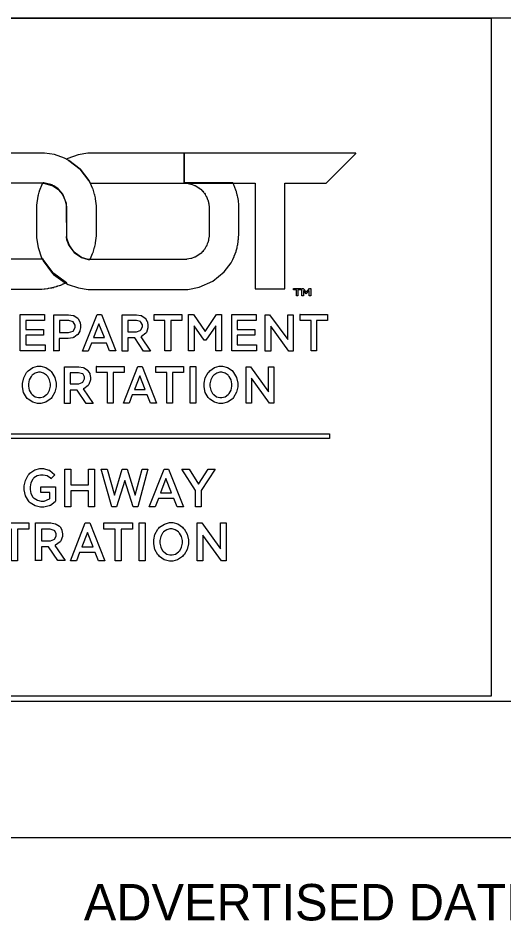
# Model space of a CAD drawing. Extents: x 0 to 34, y 0 to 22.
# Drawn here: x 28.747 to 30.08, y 2.522 to 5 of the extents above; entities that cross this region are included whole.
import ezdxf

# ---------------------------------------------------------------- set-up
doc = ezdxf.new("R2010")
doc.units = 0
for name, color, linetype in [('BORD-LINE', 7, 'Continuous'), ('MSHA-LOGO', 7, 'Continuous'), ('TTLB-TEXT', 7, 'Continuous'), ('USER-LINE', 7, 'Continuous')]:
    doc.layers.add(name, color=color, linetype=linetype)

msp = doc.modelspace()

# ---------------------------------------------------------------- linework, layer by layer
at = {"layer": 'BORD-LINE'}
for p, q in [((33.5, 5), (27.437, 5)), ((33.5, 2.75), (27.437, 2.75))]:
    msp.add_line(p, q, dxfattribs=at)
msp.add_lwpolyline([(27.437, 2.75), (27.437, 3.125), (33.5, 3.125)], dxfattribs=at)
at = {"layer": 'MSHA-LOGO'}
for points in [[(28.502, 4.5475), (28.8109, 4.5475), (28.8111, 4.5474), (28.8136, 4.547), (28.8145, 4.547), (28.817, 4.5469), (28.8399, 4.5408), (28.842, 4.5398), (28.8446, 4.5385), (28.856, 4.5303), (28.8657, 4.5202), (28.8674, 4.518), (28.8692, 4.5154), (28.8759, 4.5014), (28.8796, 4.486), (28.8798, 4.4828), (28.8798, 4.4828), (28.8798, 4.4822), (28.8798, 4.4822), (28.8798, 4.4815), (28.8798, 4.4797), (28.8798, 4.4791), (28.8798, 4.4081), (28.8798, 4.4074), (28.8798, 4.4056), (28.8798, 4.405), (28.8798, 4.405), (28.8798, 4.4045), (28.8798, 4.4045), (28.8798, 4.403), (28.8793, 4.3995), (28.8793, 4.3983), (28.8801, 4.3924), (28.8867, 4.3754), (28.901, 4.3568), (28.9214, 4.3432), (28.9399, 4.3375), (28.9439, 4.3373), (28.9446, 4.3384), (28.9451, 4.3392), (28.9451, 4.3392), (28.9458, 4.3405), (28.9518, 4.3539), (28.9524, 4.3553), (28.9529, 4.3567), (28.9572, 4.3708), (28.9576, 4.3724), (28.9577, 4.3732), (28.9595, 4.3804), (28.9596, 4.3812), (28.96, 4.3834), (28.9622, 4.4023), (28.9622, 4.4086), (28.9622, 4.4781), (28.9622, 4.485), (28.96, 4.5034), (28.9596, 4.5055), (28.9595, 4.5063), (28.9578, 4.5136), (28.9576, 4.5144), (28.9572, 4.5158), (28.9529, 4.5301), (28.9524, 4.5315), (28.9518, 4.5329), (28.9458, 4.5463), (28.9451, 4.5475), (28.9415, 4.5545), (28.9175, 4.5853), (28.8868, 4.6092), (28.8798, 4.6128), (28.8747, 4.6156), (28.8469, 4.6252), (28.8199, 4.6294), (28.8109, 4.6294), (28.5637, 4.6294)], [(28.8798, 4.4392), (28.8798, 4.4781), (28.8798, 4.4792), (28.8798, 4.4815), (28.8798, 4.4822), (28.8798, 4.4838), (28.8803, 4.4873), (28.8803, 4.4885), (28.8799, 4.4912), (28.87, 4.5163), (28.8684, 4.5185), (28.8667, 4.5209), (28.8568, 4.5312), (28.8451, 4.5395), (28.8425, 4.5408), (28.8403, 4.542), (28.8175, 4.548), (28.8151, 4.5481), (28.8151, 4.5478), (28.8145, 4.547), (28.8135, 4.5451), (28.8053, 4.5247), (28.8047, 4.5227), (28.8044, 4.522), (28.8023, 4.5146), (28.8021, 4.5139), (28.8015, 4.511), (28.7979, 4.4863), (28.7979, 4.4781), (28.7979, 4.4392), (28.7979, 4.4351)], [(29.353, 4.4781), (29.353, 4.4803), (29.3526, 4.4861), (29.3525, 4.4869), (29.3525, 4.4874), (29.3525, 4.4895), (29.3525, 4.4911), (29.3519, 4.4946), (29.3519, 4.4957), (29.3519, 4.4961), (29.3519, 4.497), (29.3519, 4.4973), (29.3519, 4.4975), (29.3519, 4.4981), (29.3519, 4.4983), (29.3518, 4.4988), (29.351, 4.504), (29.3509, 4.5045), (29.3509, 4.5051), (29.3504, 4.5062), (29.3504, 4.5066), (29.3502, 4.5072), (29.3489, 4.5128), (29.3488, 4.5133), (29.3488, 4.5139), (29.3488, 4.5144), (29.3486, 4.5152), (29.3465, 4.5229), (29.3463, 4.5237), (29.3459, 4.525), (29.341, 4.5379), (29.3405, 4.5392), (29.3403, 4.5399), (29.3372, 4.5464), (29.3369, 4.547), (29.3369, 4.5473), (29.3364, 4.5481), (29.2053, 4.5481), (29.2048, 4.547), (29.2063, 4.547), (29.2068, 4.547), (29.2075, 4.547), (29.2092, 4.5466), (29.2094, 4.5465), (29.2105, 4.5464), (29.221, 4.5443), (29.2219, 4.5439), (29.2228, 4.5437), (29.2313, 4.5407), (29.2322, 4.5403), (29.2328, 4.54), (29.2374, 4.5375), (29.2379, 4.5372), (29.2383, 4.5372), (29.2384, 4.5372), (29.2388, 4.5369), (29.2432, 4.5343), (29.2436, 4.534), (29.2441, 4.5337), (29.2441, 4.5335), (29.2445, 4.5333), (29.2484, 4.5303), (29.2488, 4.5299), (29.2493, 4.5294), (29.2497, 4.5292), (29.2527, 4.526), (29.253, 4.5258), (29.2533, 4.5253), (29.2535, 4.5253), (29.254, 4.5247), (29.2542, 4.5245), (29.2564, 4.5219), (29.2566, 4.5216), (29.2571, 4.5211), (29.2572, 4.521), (29.258, 4.5197), (29.2582, 4.5196), (29.2584, 4.5193), (29.2606, 4.5162), (29.2607, 4.5159), (29.2609, 4.5158), (29.2616, 4.5141), (29.2618, 4.5139), (29.2621, 4.5133), (29.2623, 4.5133), (29.2624, 4.5131), (29.2637, 4.5105), (29.2639, 4.5102), (29.2639, 4.51), (29.2647, 4.5079), (29.2649, 4.5076), (29.265, 4.5074), (29.2663, 4.5044), (29.2664, 4.504), (29.2665, 4.5039), (29.2669, 4.5019), (29.2669, 4.5017), (29.2673, 4.501), (29.2675, 4.5009), (29.2676, 4.5007), (29.2685, 4.4985), (29.2685, 4.4978), (29.2686, 4.4975), (29.2694, 4.4944), (29.2695, 4.4942), (29.2695, 4.4934), (29.2701, 4.4916), (29.2701, 4.4911), (29.2702, 4.4907), (29.2706, 4.4878), (29.2706, 4.4869), (29.2706, 4.4862), (29.2711, 4.4848), (29.2711, 4.4843), (29.2711, 4.4826), (29.2716, 4.4789), (29.2716, 4.4776), (29.2716, 4.4066), (29.2716, 4.4049), (29.2712, 4.4004), (29.2711, 4.3998), (29.2711, 4.3992), (29.2707, 4.3975), (29.2706, 4.3973), (29.2706, 4.3962), (29.2701, 4.3939), (29.2701, 4.3931), (29.2701, 4.3923), (29.2695, 4.3906), (29.2695, 4.39), (29.2694, 4.3897), (29.2686, 4.3866), (29.2685, 4.3864), (29.2684, 4.3861), (29.2676, 4.3835), (29.2675, 4.3832), (29.2675, 4.383), (29.2671, 4.3824), (29.2669, 4.3822), (29.2664, 4.3807), (29.2664, 4.3801), (29.2663, 4.3799), (29.265, 4.3769), (29.2649, 4.3765), (29.2647, 4.3763), (29.2639, 4.3742), (29.2639, 4.3739), (29.2637, 4.3737), (29.2624, 4.3711), (29.2623, 4.3708), (29.2619, 4.3703), (29.2618, 4.3703), (29.2616, 4.3702), (29.2609, 4.3685), (29.2607, 4.3682), (29.2605, 4.368), (29.2584, 4.3649), (29.2582, 4.3646), (29.258, 4.3645), (29.2572, 4.3632), (29.2571, 4.363), (29.2566, 4.3625), (29.2563, 4.3623), (29.2541, 4.3597), (29.254, 4.3594), (29.2535, 4.3589), (29.2531, 4.3584), (29.253, 4.3584), (29.2527, 4.3581), (29.2496, 4.355), (29.2493, 4.3547), (29.2488, 4.3542), (29.2484, 4.354), (29.2445, 4.3509), (29.2441, 4.3506), (29.2436, 4.3502), (29.2436, 4.3501), (29.2432, 4.3498), (29.239, 4.3472), (29.2384, 4.347), (29.238, 4.347), (29.2379, 4.347), (29.2375, 4.3467), (29.2328, 4.3441), (29.2322, 4.3439), (29.2315, 4.3435), (29.2228, 4.3405), (29.2219, 4.3402), (29.2208, 4.34), (29.2105, 4.3378), (29.2094, 4.3377), (29.2088, 4.3377), (29.2071, 4.3373), (29.2068, 4.3371), (29.2059, 4.3371), (29.2039, 4.3371), (29.2032, 4.3371), (28.9498, 4.3371), (28.9489, 4.3371), (28.9468, 4.3371), (28.9462, 4.3371), (28.9399, 4.3375), (28.9214, 4.3432), (28.9011, 4.3573), (28.887, 4.3774), (28.8812, 4.3957), (28.8809, 4.4019), (28.8809, 4.403), (28.8809, 4.4053), (28.8809, 4.4061), (28.8809, 4.4392), (28.8798, 4.4392)], [(28.7979, 4.4351), (28.7979, 4.4061), (28.7979, 4.3971), (28.8023, 4.37), (28.8119, 4.3423), (28.8145, 4.3371), (28.8163, 4.3336), (28.8393, 4.3022), (28.842, 4.2993), (28.8447, 4.2966), (28.8763, 4.2737), (28.8798, 4.2718), (28.885, 4.2691), (28.9127, 4.2595), (28.9397, 4.2553), (28.9487, 4.2553), (29.2022, 4.2553), (29.2127, 4.2553), (29.2443, 4.2612), (29.2817, 4.2779), (29.3129, 4.3038), (29.3317, 4.3282), (29.3364, 4.3371), (29.3368, 4.3378), (29.3397, 4.3442), (29.34, 4.3449), (29.3405, 4.3462), (29.3453, 4.3591), (29.3457, 4.3604), (29.346, 4.3612), (29.3482, 4.369), (29.3483, 4.3698), (29.3483, 4.3703), (29.3483, 4.3708), (29.3484, 4.3713), (29.3497, 4.377), (29.3499, 4.3776), (29.3499, 4.3781), (29.3504, 4.3793), (29.3504, 4.3796), (29.3505, 4.3802), (29.3513, 4.3853), (29.3514, 4.3858), (29.3514, 4.3861), (29.3514, 4.3867), (29.3514, 4.3869), (29.3514, 4.3873), (29.3514, 4.3882), (29.3514, 4.3884), (29.3514, 4.39), (29.3519, 4.3935), (29.3519, 4.3947), (29.3519, 4.3967), (29.3519, 4.3973), (29.3519, 4.3995), (29.3525, 4.4044), (29.3525, 4.4061), (29.353, 4.4781)], [(28.4062, 4.2563), (28.8104, 4.2563), (28.8127, 4.2563), (28.8189, 4.2567), (28.8197, 4.2568), (28.8219, 4.2568), (28.8277, 4.2577), (28.8285, 4.2578), (28.8292, 4.2578), (28.8306, 4.2584), (28.8311, 4.2584), (28.8316, 4.2585), (28.8363, 4.2593), (28.8368, 4.2594), (28.8376, 4.2594), (28.8393, 4.2599), (28.8399, 4.2599), (28.8403, 4.2601), (28.8447, 4.2608), (28.8451, 4.2609), (28.8453, 4.2611), (28.8479, 4.2619), (28.8482, 4.262), (28.8486, 4.2621), (28.8525, 4.2634), (28.8529, 4.2635), (28.8531, 4.2637), (28.8557, 4.2645), (28.856, 4.2646), (28.8564, 4.2647), (28.8602, 4.266), (28.8606, 4.2661), (28.8609, 4.2663), (28.8635, 4.2671), (28.8637, 4.2672), (28.8641, 4.2673), (28.8685, 4.2691), (28.8689, 4.2692), (28.8692, 4.2694), (28.8712, 4.2702), (28.8715, 4.2703), (28.8722, 4.2706), (28.8782, 4.2735), (28.8788, 4.2739), (28.8792, 4.2737), (28.8808, 4.2734), (28.8814, 4.2734), (28.8811, 4.2734), (28.8805, 4.2738), (28.8803, 4.2739), (28.8768, 4.2757), (28.8457, 4.2985), (28.843, 4.3014), (28.8403, 4.3041), (28.8179, 4.3348), (28.8161, 4.3382), (28.8157, 4.3382), (28.8148, 4.3382), (28.8145, 4.3382), (28.8136, 4.3382), (28.8116, 4.3382), (28.8109, 4.3382), (28.5108, 4.3382)]]:
    msp.add_lwpolyline(points, dxfattribs=at)
for points in [[(28.9457, 4.5465), (28.947, 4.5465), (28.9477, 4.5465), (29.2011, 4.5465), (29.2015, 4.5465), (29.2024, 4.5465), (29.2027, 4.5465), (29.2032, 4.5475), (29.2032, 4.6289), (29.2031, 4.6289), (29.2016, 4.6289), (29.2011, 4.6289), (28.9477, 4.6289), (28.9387, 4.6289), (28.9117, 4.6245), (28.884, 4.6149), (28.8799, 4.6128), (28.8868, 4.6092), (28.9175, 4.5853), (28.9415, 4.5545), (28.9451, 4.5475)], [(29.2032, 4.6289), (29.2032, 4.547), (29.3975, 4.547), (29.3975, 4.2568), (29.4789, 4.2568), (29.4789, 4.547), (29.5924, 4.547), (29.6738, 4.6284), (29.6738, 4.6289)], [(29.5027, 4.2577), (29.5229, 4.2577), (29.5229, 4.2541), (29.5151, 4.2541), (29.5151, 4.2375), (29.511, 4.2375), (29.511, 4.2541), (29.5027, 4.2541)], [(29.526, 4.2577), (29.5297, 4.2577), (29.5384, 4.2479), (29.5467, 4.2577), (29.5504, 4.2577), (29.5504, 4.2375), (29.5457, 4.2375), (29.5457, 4.252), (29.5379, 4.2427), (29.5302, 4.252), (29.5302, 4.2375), (29.526, 4.2375)], [(28.7529, 4.1863), (28.8197, 4.1863), (28.8197, 4.1703), (28.7684, 4.1703), (28.7684, 4.1449), (28.8166, 4.1449), (28.8166, 4.1293), (28.7684, 4.1293), (28.7684, 4.1029), (28.8213, 4.1029), (28.8213, 4.0868), (28.7529, 4.0868)], [(28.8451, 4.0858), (28.8451, 4.1858), (28.8814, 4.1858), (28.886, 4.1858), (28.8987, 4.1836), (28.9, 4.1832), (28.9013, 4.1827), (28.9108, 4.1762), (28.9114, 4.1754), (28.9121, 4.1747), (28.9169, 4.166), (28.9171, 4.1651), (28.9174, 4.1642), (28.9187, 4.1559), (28.9187, 4.1531), (28.9187, 4.1502), (28.917, 4.1422), (28.9166, 4.1412), (28.9162, 4.1404), (28.911, 4.1317), (28.9104, 4.1309), (28.9097, 4.1301), (28.8998, 4.1236), (28.8985, 4.1231), (28.8972, 4.1226), (28.8849, 4.1205), (28.8809, 4.1205), (28.8601, 4.1205), (28.8601, 4.0863), (28.8451, 4.0863)], [(28.8612, 4.1703), (28.8612, 4.1366), (28.8819, 4.1366), (28.886, 4.1366), (28.8982, 4.1409), (28.9037, 4.1505), (28.9037, 4.1537), (28.9037, 4.1568), (28.8985, 4.1661), (28.8868, 4.1703), (28.8829, 4.1703)], [(28.9638, 4.1863), (28.9757, 4.1863), (29.0151, 4.0863), (28.9985, 4.0863), (28.9897, 4.1081), (28.9487, 4.1081), (28.9399, 4.0858), (28.9239, 4.0858)], [(29.0327, 4.0858), (29.0327, 4.1858), (29.0679, 4.1858), (29.0723, 4.1858), (29.0843, 4.1836), (29.0856, 4.1832), (29.0867, 4.1828), (29.0958, 4.1767), (29.0964, 4.176), (29.0971, 4.1752), (29.1017, 4.167), (29.1021, 4.1661), (29.1024, 4.1652), (29.1037, 4.1569), (29.1037, 4.1542), (29.1037, 4.1497), (29.0994, 4.1374), (29.0985, 4.1361), (29.0976, 4.1348), (29.0855, 4.1257), (29.084, 4.1252), (29.111, 4.0853), (29.0918, 4.0853), (29.0674, 4.122), (29.0483, 4.122), (29.0483, 4.0853), (29.0327, 4.0853)], [(29.0488, 4.1697), (29.0488, 4.1392), (29.069, 4.1392), (29.0725, 4.1392), (29.0821, 4.1427), (29.083, 4.1433), (29.0837, 4.144), (29.0882, 4.1524), (29.0882, 4.1552), (29.0882, 4.1579), (29.0842, 4.1654), (29.0835, 4.1661), (29.0827, 4.1667), (29.072, 4.1697), (29.0685, 4.1697)], [(29.1203, 4.1863), (29.1965, 4.1863), (29.1965, 4.1703), (29.1659, 4.1703), (29.1659, 4.0863), (29.1503, 4.0863), (29.1503, 4.1703), (29.1203, 4.1703)], [(29.2146, 4.1863), (29.2286, 4.1863), (29.2607, 4.1397), (29.2918, 4.1863), (29.3053, 4.1863), (29.3053, 4.0863), (29.2898, 4.0863), (29.2898, 4.1557), (29.2623, 4.1158), (29.2582, 4.1158), (29.2302, 4.1557), (29.2302, 4.0863), (29.2146, 4.0863)], [(29.3333, 4.1863), (29.4001, 4.1863), (29.4001, 4.1703), (29.3488, 4.1703), (29.3488, 4.1449), (29.397, 4.1449), (29.397, 4.1293), (29.3488, 4.1293), (29.3488, 4.1029), (29.4017, 4.1029), (29.4017, 4.0868), (29.3333, 4.0868)], [(29.4903, 4.0858), (29.4406, 4.1542), (29.4406, 4.0858), (29.4255, 4.0858), (29.4255, 4.1858), (29.4375, 4.1858), (29.4872, 4.1174), (29.4872, 4.1858), (29.5022, 4.1858), (29.5022, 4.0858)], [(29.5204, 4.1863), (29.5965, 4.1863), (29.5965, 4.1703), (29.5665, 4.1703), (29.5665, 4.0863), (29.551, 4.0863), (29.551, 4.1703), (29.5209, 4.1703), (29.5209, 4.1863)], [(28.9544, 4.1231), (28.984, 4.1231), (28.969, 4.1609)], [(28.7725, 4.0293), (28.7747, 4.0318), (28.7873, 4.0405), (28.8007, 4.0443), (28.8052, 4.0443), (28.8097, 4.0443), (28.8231, 4.0408), (28.8356, 4.0323), (28.8378, 4.0298), (28.84, 4.0274), (28.8479, 4.0134), (28.8513, 3.9981), (28.8513, 3.993), (28.8513, 3.988), (28.8479, 3.9729), (28.84, 3.9587), (28.8378, 3.9562), (28.8356, 3.9538), (28.8231, 3.9453), (28.8097, 3.9417), (28.8052, 3.9417), (28.8007, 3.9417), (28.7873, 3.9453), (28.7747, 3.9538), (28.7725, 3.9562), (28.7703, 3.9587), (28.7625, 3.9727), (28.7591, 3.988), (28.7591, 3.993), (28.7592, 3.9967), (28.7627, 4.0129), (28.7703, 4.0268)], [(28.8747, 3.9427), (28.8747, 4.0428), (28.9099, 4.0428), (28.9143, 4.0428), (28.9262, 4.0406), (28.9275, 4.0402), (28.9287, 4.0398), (28.9377, 4.0337), (28.9384, 4.0329), (28.939, 4.0322), (28.9437, 4.024), (28.9441, 4.0231), (28.9443, 4.0222), (28.9456, 4.0139), (28.9456, 4.0112), (28.9456, 4.0066), (28.9413, 3.9943), (28.9405, 3.993), (28.9395, 3.9917), (28.9275, 3.9827), (28.9259, 3.9821), (28.9529, 3.9422), (28.9337, 3.9422), (28.9094, 3.979), (28.8902, 3.979), (28.8902, 3.9422), (28.8747, 3.9422)], [(28.9617, 4.0433), (29.0379, 4.0433), (29.0379, 4.0272), (29.0078, 4.0272), (29.0078, 3.9433), (28.9923, 3.9433), (28.9923, 4.0272), (28.9622, 4.0272), (28.9622, 4.0433)], [(29.0757, 4.0433), (29.0876, 4.0433), (29.127, 3.9433), (29.1105, 3.9433), (29.1016, 3.9655), (29.0607, 3.9655), (29.0519, 3.9433), (29.0363, 3.9433)], [(29.1249, 4.0433), (29.2011, 4.0433), (29.2011, 4.0272), (29.1711, 4.0272), (29.1711, 3.9433), (29.1555, 3.9433), (29.1555, 4.0272), (29.1255, 4.0272), (29.1255, 4.0433)], [(29.2193, 4.0433), (29.2348, 4.0433), (29.2348, 3.9433), (29.2193, 3.9433)], [(29.2711, 4.0293), (29.2733, 4.0318), (29.2858, 4.0405), (29.2993, 4.0443), (29.3037, 4.0443), (29.3082, 4.0443), (29.3216, 4.0408), (29.3342, 4.0323), (29.3364, 4.0298), (29.3386, 4.0274), (29.3464, 4.0134), (29.3499, 3.9981), (29.3499, 3.993), (29.3499, 3.988), (29.3464, 3.9729), (29.3386, 3.9587), (29.3364, 3.9562), (29.3342, 3.9538), (29.3216, 3.9453), (29.3082, 3.9417), (29.3037, 3.9417), (29.2993, 3.9417), (29.2858, 3.9453), (29.2733, 3.9538), (29.2711, 3.9562), (29.2689, 3.9587), (29.261, 3.9727), (29.2576, 3.988), (29.2576, 3.993), (29.2576, 3.998), (29.2609, 4.0129), (29.2688, 4.0268)], [(29.4375, 3.9427), (29.3877, 4.0112), (29.3877, 3.9427), (29.3727, 3.9427), (29.3727, 4.0428), (29.3846, 4.0428), (29.4344, 3.9744), (29.4344, 4.0428), (29.4494, 4.0428), (29.4494, 3.9427)], [(28.7845, 3.9681), (28.7859, 3.9665), (28.7941, 3.9607), (28.8028, 3.9583), (28.8057, 3.9583), (28.8086, 3.9583), (28.8173, 3.9607), (28.8255, 3.9665), (28.827, 3.9681), (28.8284, 3.9697), (28.8335, 3.979), (28.8358, 3.9895), (28.8358, 3.993), (28.8358, 3.9965), (28.8335, 4.007), (28.8284, 4.0163), (28.827, 4.0179), (28.8255, 4.0196), (28.8173, 4.0254), (28.8086, 4.0277), (28.8057, 4.0277), (28.8029, 4.0277), (28.7943, 4.0254), (28.786, 4.0196), (28.7845, 4.0179), (28.783, 4.0163), (28.7779, 4.007), (28.7756, 3.9965), (28.7756, 3.993), (28.7756, 3.9895), (28.7777, 3.979), (28.7829, 3.9697)], [(28.8902, 4.0267), (28.8902, 3.9961), (28.9104, 3.9961), (28.9139, 3.9961), (28.9235, 3.9996), (28.9244, 4.0003), (28.9252, 4.0009), (28.9296, 4.0094), (28.9296, 4.0122), (28.9296, 4.0149), (28.9257, 4.0224), (28.9249, 4.0231), (28.9241, 4.0237), (28.9134, 4.0267), (28.9099, 4.0267)], [(29.0664, 3.9801), (29.0959, 3.9801), (29.0809, 4.0179)], [(29.2825, 3.9681), (29.2839, 3.9665), (29.2921, 3.9607), (29.3008, 3.9583), (29.3037, 3.9583), (29.3066, 3.9583), (29.3153, 3.9607), (29.3236, 3.9665), (29.325, 3.9681), (29.3264, 3.9697), (29.3315, 3.979), (29.3338, 3.9895), (29.3338, 3.993), (29.3338, 3.9965), (29.3315, 4.007), (29.3264, 4.0163), (29.325, 4.0179), (29.3236, 4.0196), (29.3153, 4.0254), (29.3066, 4.0277), (29.3037, 4.0277), (29.3009, 4.0277), (29.2923, 4.0254), (29.284, 4.0196), (29.2825, 4.0179), (29.2811, 4.0163), (29.2759, 4.007), (29.2737, 3.9965), (29.2737, 3.993), (29.2737, 3.9895), (29.2759, 3.979), (29.2811, 3.9697)], [(27.8081, 3.8588), (29.6017, 3.8588), (29.6017, 3.8458), (27.8081, 3.8458)], [(28.8099, 3.7137), (28.8503, 3.7137), (28.8503, 3.6738), (28.8492, 3.6725), (28.8358, 3.6625), (28.8342, 3.6619), (28.8325, 3.6611), (28.8182, 3.6577), (28.8135, 3.6577), (28.8085, 3.6577), (28.7937, 3.6613), (28.78, 3.6698), (28.7777, 3.6722), (28.7754, 3.6747), (28.7672, 3.6891), (28.7637, 3.7052), (28.7637, 3.7106), (28.7637, 3.7158), (28.7672, 3.7312), (28.775, 3.7458), (28.7772, 3.7484), (28.7795, 3.751), (28.7928, 3.7598), (28.8067, 3.7634), (28.8114, 3.7634), (28.8168, 3.7634), (28.8315, 3.7595), (28.8332, 3.7588), (28.8347, 3.758), (28.8473, 3.7476), (28.8482, 3.7463), (28.8373, 3.7349), (28.8359, 3.7368), (28.8268, 3.7431), (28.8161, 3.7458), (28.8125, 3.7458), (28.8091, 3.7458), (28.7992, 3.7434), (28.7905, 3.7377), (28.7891, 3.736), (28.7877, 3.7344), (28.7826, 3.7248), (28.7803, 3.7137), (28.7803, 3.71), (28.7803, 3.7063), (28.7826, 3.6951), (28.7881, 3.6853), (28.7897, 3.6836), (28.7912, 3.6821), (28.8002, 3.6767), (28.8101, 3.6743), (28.8135, 3.6743), (28.8188, 3.6743), (28.8333, 3.6804), (28.8347, 3.6815), (28.8347, 3.6976), (28.8099, 3.6976)], [(28.9405, 3.7023), (28.8917, 3.7023), (28.8917, 3.6582), (28.8757, 3.6582), (28.8757, 3.7619), (28.8917, 3.7619), (28.8917, 3.7189), (28.9405, 3.7189), (28.9405, 3.7619), (28.9565, 3.7619), (28.9565, 3.6582), (28.9405, 3.6582)], [(29.0762, 3.6582), (29.0628, 3.6582), (29.0399, 3.7303), (29.0177, 3.6582), (29.0042, 3.6582), (28.9752, 3.7619), (28.9918, 3.7619), (29.0114, 3.6904), (29.0332, 3.7619), (29.0462, 3.7619), (29.0685, 3.6904), (29.0876, 3.7619), (29.1037, 3.7619)], [(29.1478, 3.7619), (29.1602, 3.7619), (29.2011, 3.6582), (29.184, 3.6582), (29.1747, 3.681), (29.1322, 3.681), (29.1234, 3.6582), (29.1068, 3.6582)], [(29.2498, 3.7033), (29.2498, 3.6582), (29.2338, 3.6582), (29.2338, 3.7033), (29.1965, 3.7619), (29.2167, 3.7619), (29.2426, 3.7204), (29.269, 3.7619), (29.2882, 3.7619)], [(29.1379, 3.6966), (29.1685, 3.6966), (29.1529, 3.736)], [(28.6979, 3.6142), (28.7767, 3.6142), (28.7767, 3.5971), (28.7456, 3.5971), (28.7456, 3.5105), (28.7295, 3.5105), (28.7295, 3.5971), (28.6985, 3.5971), (28.6985, 3.6142)], [(28.7954, 3.5105), (28.7954, 3.6142), (28.8321, 3.6142), (28.8367, 3.6142), (28.849, 3.612), (28.8503, 3.6116), (28.8516, 3.6112), (28.861, 3.6051), (28.8617, 3.6043), (28.8623, 3.6036), (28.8671, 3.5949), (28.8674, 3.594), (28.8676, 3.5931), (28.8689, 3.5848), (28.8689, 3.5821), (28.8689, 3.5774), (28.8641, 3.5647), (28.8632, 3.5634), (28.8623, 3.5621), (28.8497, 3.5529), (28.8482, 3.5525), (28.8762, 3.5111), (28.8565, 3.5111), (28.8311, 3.5489), (28.8114, 3.5489), (28.8114, 3.5111), (28.7954, 3.5111)], [(28.8114, 3.5971), (28.8114, 3.5655), (28.8321, 3.5655), (28.8358, 3.5655), (28.8457, 3.569), (28.8467, 3.5696), (28.8476, 3.5704), (28.8518, 3.5788), (28.8518, 3.5815), (28.8518, 3.5844), (28.8479, 3.5923), (28.8472, 3.5929), (28.8464, 3.5936), (28.8353, 3.5971), (28.8316, 3.5971)], [(28.9317, 3.6142), (28.9441, 3.6142), (28.985, 3.5105), (28.9679, 3.5105), (28.9586, 3.5333), (28.9161, 3.5333), (28.9073, 3.5105), (28.8907, 3.5105)], [(28.9824, 3.6142), (29.0612, 3.6142), (29.0612, 3.5971), (29.0301, 3.5971), (29.0301, 3.5105), (29.014, 3.5105), (29.014, 3.5971), (28.9829, 3.5971), (28.9829, 3.6142)], [(29.0799, 3.6142), (29.0959, 3.6142), (29.0959, 3.5105), (29.0799, 3.5105)], [(29.1332, 3.5997), (29.1356, 3.6023), (29.1487, 3.6113), (29.1624, 3.6152), (29.1669, 3.6152), (29.1715, 3.6152), (29.1853, 3.6114), (29.1984, 3.6027), (29.2006, 3.6002), (29.2028, 3.5977), (29.2109, 3.5832), (29.2146, 3.5676), (29.2146, 3.5623), (29.2146, 3.5572), (29.2111, 3.5417), (29.2029, 3.5271), (29.2006, 3.5245), (29.1983, 3.5219), (29.1851, 3.5131), (29.1715, 3.5095), (29.1669, 3.5095), (29.1623, 3.5095), (29.1483, 3.5133), (29.1354, 3.5221), (29.1332, 3.5245), (29.1309, 3.527), (29.1227, 3.5415), (29.1193, 3.5571), (29.1193, 3.5623), (29.1193, 3.5675), (29.1227, 3.5828), (29.1309, 3.5972)], [(29.1452, 3.5364), (29.1467, 3.5348), (29.1553, 3.529), (29.164, 3.5266), (29.1669, 3.5266), (29.1699, 3.5266), (29.179, 3.529), (29.1876, 3.5348), (29.1892, 3.5364), (29.1908, 3.5381), (29.1959, 3.5479), (29.198, 3.5587), (29.198, 3.5623), (29.198, 3.5659), (29.1957, 3.5767), (29.1902, 3.5866), (29.1887, 3.5883), (29.1871, 3.59), (29.1786, 3.5957), (29.1698, 3.5981), (29.1669, 3.5981), (29.1639, 3.5981), (29.1551, 3.5957), (29.1466, 3.59), (29.1452, 3.5883), (29.1437, 3.5866), (29.1386, 3.5769), (29.1364, 3.566), (29.1364, 3.5623), (29.1364, 3.5587), (29.1386, 3.5479), (29.1437, 3.5381)], [(29.3058, 3.5105), (29.2545, 3.581), (29.2545, 3.5105), (29.239, 3.5105), (29.239, 3.6142), (29.2514, 3.6142), (29.3027, 3.5432), (29.3027, 3.6142), (29.3183, 3.6142), (29.3183, 3.5105)], [(28.9223, 3.5489), (28.9529, 3.5489), (28.9374, 3.5883)]]:
    msp.add_lwpolyline(points, close=True, dxfattribs=at)
at = {"layer": 'USER-LINE'}
msp.add_lwpolyline([(27.437, 5), (30.0454, 5), (30.0454, 3.1389), (27.437, 3.1389)], close=True, dxfattribs=at)

# ---------------------------------------------------------------- texts
at = {"layer": 'TTLB-TEXT'}
msp.add_text('ADVERTISED DATE', height=0.1, dxfattribs=at).set_placement((28.9276, 2.5233))

doc.saveas('drawing.dxf')
